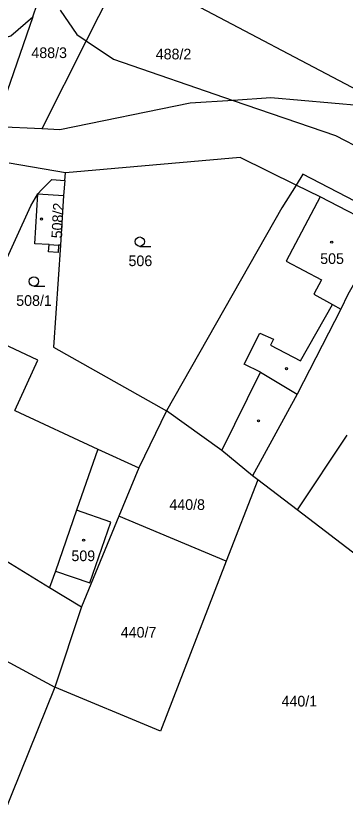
# Model space of a CAD drawing. Extents: x -776701 to -776081, y -974398 to -973771.
# Drawn here: x -776283.6 to -776231, y -974390.3 to -974262.5 of the extents above; entities that cross this region are included whole.
import ezdxf

# ---------------------------------------------------------------- set-up
doc = ezdxf.new("R2010")
doc.units = 0
for name, color, linetype in [('Hranice parcel', 7, 'Continuous'), ('Parcelní čísla', 7, 'Continuous'), ('Vnitřní kresba', 7, 'Continuous'), ('Značky budov', 7, 'Continuous'), ('Značky kultur', 7, 'Continuous')]:
    doc.layers.add(name, color=color, linetype=linetype)

msp = doc.modelspace()

# ---------------------------------------------------------------- linework, layer by layer
at = {"layer": 'Hranice parcel'}
for p, q in [((-776266.43, -974254.64), (-776223.5, -974277.28)), ((-776280.95, -974262.62), (-776287.02, -974280.17)), ((-776279.48, -974280.55), (-776287.02, -974280.17)), ((-776275.72, -974287.55), (-776284.72, -974286.01)), ((-776275.8, -974288.77), (-776275.72, -974287.55)), ((-776275.8, -974288.77), (-776276.03, -974291.16)), ((-776276.03, -974291.16), (-776276.52, -974299.13)), ((-776283.82, -974325.55), (-776270.54, -974331.71)), ((-776259.54, -974325.58), (-776264.01, -974334.7)), ((-776230.76, -974329.49), (-776238.68, -974341.4)), ((-776270.54, -974331.71), (-776264.01, -974334.7)), ((-776264.01, -974334.7), (-776267.19, -974342.43)), ((-776244.97, -974336.58), (-776245.8, -974335.94)), ((-776244.97, -974336.58), (-776250, -974349.58)), ((-776238.68, -974341.4), (-776244.97, -974336.58)), ((-776302.5, -974339.06), (-776278.24, -974353.79)), ((-776223.09, -974353.36), (-776238.68, -974341.4)), ((-776267.19, -974342.43), (-776273.13, -974356.9)), ((-776250, -974349.58), (-776267.19, -974342.43)), ((-776250, -974349.58), (-776260.51, -974376.74)), ((-776308.85, -974352.8), (-776277.4, -974369.72)), ((-776278.24, -974353.79), (-776273.13, -974356.9)), ((-776273.13, -974356.9), (-776277.4, -974369.72)), ((-776277.4, -974369.72), (-776285.72, -974390.31)), ((-776260.51, -974376.74), (-776277.4, -974369.72))]:
    msp.add_line(p, q, dxfattribs=at)
for points in [[(-776280.95, -974262.62), (-776278.84, -974256.52), (-776273.87, -974250.3)], [(-776266.43, -974254.64), (-776272.39, -974266.46), (-776279.48, -974280.55)], [(-776322.34, -974263.94), (-776305.38, -974269.65), (-776296.22, -974269.13), (-776284.45, -974265.69), (-776280.95, -974262.62)], [(-776223.5, -974277.28), (-776242.86, -974275.59), (-776248.91, -974275.98), (-776255.78, -974276.42), (-776276.61, -974280.69), (-776279.48, -974280.55)], [(-776238.85, -974289.51), (-776247.8, -974285.11), (-776275.72, -974287.55)], [(-776280.11, -974290.91), (-776279.5, -974290.24), (-776277.87, -974288.61), (-776275.8, -974288.77)], [(-776238.85, -974289.51), (-776241.13, -974293.17), (-776259.54, -974325.58)], [(-776224.73, -974296.72), (-776234.99, -974291.41), (-776238.85, -974289.51)], [(-776294.07, -974320.91), (-776281.24, -974292.8), (-776280.11, -974290.91)], [(-776276.52, -974299.13), (-776276.81, -974299.11), (-776276.88, -974300.26), (-776278.41, -974300.18), (-776278.34, -974299.03), (-776280.61, -974298.9), (-776280.11, -974290.91)], [(-776224.73, -974296.72), (-776230.59, -974306.97), (-776231.7, -974309.35), (-776238.7, -974322.9), (-776245.8, -974335.94)], [(-776276.52, -974299.13), (-776277.63, -974315.42), (-776259.54, -974325.58)], [(-776283.82, -974325.55), (-776280.13, -974317.46), (-776287.54, -974314), (-776291.26, -974322.16)], [(-776245.8, -974335.94), (-776250.74, -974331.91), (-776259.54, -974325.58)], [(-776270.54, -974331.71), (-776273.94, -974341.46), (-776277.33, -974351.17), (-776278.24, -974353.79)]]:
    msp.add_lwpolyline(points, dxfattribs=at)
at = {"layer": 'Vnitřní kresba'}
for p, q in [((-776276.57, -974261.56), (-776273.88, -974265.46)), ((-776273.88, -974265.46), (-776272.39, -974266.46)), ((-776272.39, -974266.46), (-776268.01, -974269.4)), ((-776268.01, -974269.4), (-776248.91, -974275.98)), ((-776248.91, -974275.98), (-776232.56, -974281.61)), ((-776232.56, -974281.61), (-776219.62, -974288.25)), ((-776237.75, -974287.75), (-776238.85, -974289.51)), ((-776213.06, -974300.66), (-776237.75, -974287.75)), ((-776280.11, -974290.91), (-776276.03, -974291.16)), ((-776234.99, -974291.41), (-776240.43, -974301.68)), ((-776278.34, -974299.03), (-776276.81, -974299.11)), ((-776240.43, -974301.68), (-776234.8, -974304.67)), ((-776234.8, -974304.67), (-776236.01, -974306.92)), ((-776236.01, -974306.92), (-776233, -974308.6)), ((-776238.14, -974317.59), (-776233, -974308.6)), ((-776233, -974308.6), (-776231.7, -974309.35)), ((-776247.13, -974318.14), (-776244.62, -974313.15)), ((-776244.62, -974313.15), (-776242.47, -974314.15)), ((-776242.47, -974314.15), (-776242.96, -974315.09)), ((-776242.96, -974315.09), (-776238.14, -974317.59)), ((-776244.53, -974319.39), (-776247.13, -974318.14)), ((-776250.74, -974331.91), (-776244.53, -974319.39)), ((-776244.53, -974319.39), (-776238.7, -974322.9)), ((-776268.45, -974343.37), (-776273.94, -974341.46)), ((-776271.83, -974353.08), (-776268.45, -974343.37)), ((-776277.33, -974351.17), (-776271.83, -974353.08))]:
    msp.add_line(p, q, dxfattribs=at)
at = {"layer": 'Značky budov'}
for centre in [(-776279.55, -974294.93), (-776233.15, -974298.64), (-776240.38, -974318.85), (-776244.85, -974327.17), (-776272.81, -974346.25)]:
    msp.add_circle(centre, 0.175, dxfattribs=at)
at = {"layer": 'Značky kultur'}
for p, q in [((-776263.83, -974299.3), (-776262.08, -974299.3)), ((-776280.75, -974305.65), (-776279, -974305.65))]:
    msp.add_line(p, q, dxfattribs=at)
for centre in [(-776263.83, -974298.55), (-776280.75, -974304.9)]:
    msp.add_circle(centre, 0.75, dxfattribs=at)

# ---------------------------------------------------------------- texts
at = {"layer": 'Parcelní čísla'}
for s, p in [('488/3', (-776281.16, -974269.22)), ('488/2', (-776261.28, -974269.43)), ('505', (-776234.99, -974302.11)), ('506', (-776265.63, -974302.46)), ('508/1', (-776283.58, -974308.81)), ('440/8', (-776259.1, -974341.41)), ('509', (-776274.76, -974349.59)), ('440/7', (-776266.87, -974361.81)), ('440/1', (-776241.17, -974372.81))]:
    msp.add_text(s, height=1.7, dxfattribs=at).set_placement(p)
msp.add_text('508/2', height=1.7, rotation=87, dxfattribs=at).set_placement((-776276.27, -974298.06))

doc.saveas('drawing.dxf')
